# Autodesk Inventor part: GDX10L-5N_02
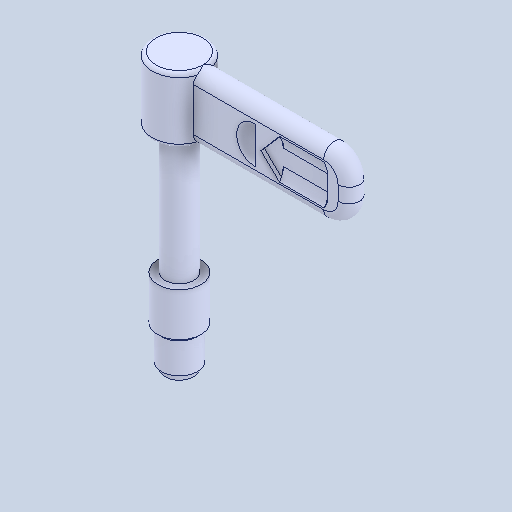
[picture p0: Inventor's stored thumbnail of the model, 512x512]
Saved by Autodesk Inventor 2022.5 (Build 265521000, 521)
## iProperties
Created: 2024-06
Part Number: GDX10L-5N_02
Material: 一般
Document SubType Name: Modeling
Designer: ImaoCorp
Density: 1 g/cm^3
Appearance: 既定
Author: ImaoCorp
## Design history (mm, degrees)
feature "GDX10L-5N_02"
node "ソリッド1"
